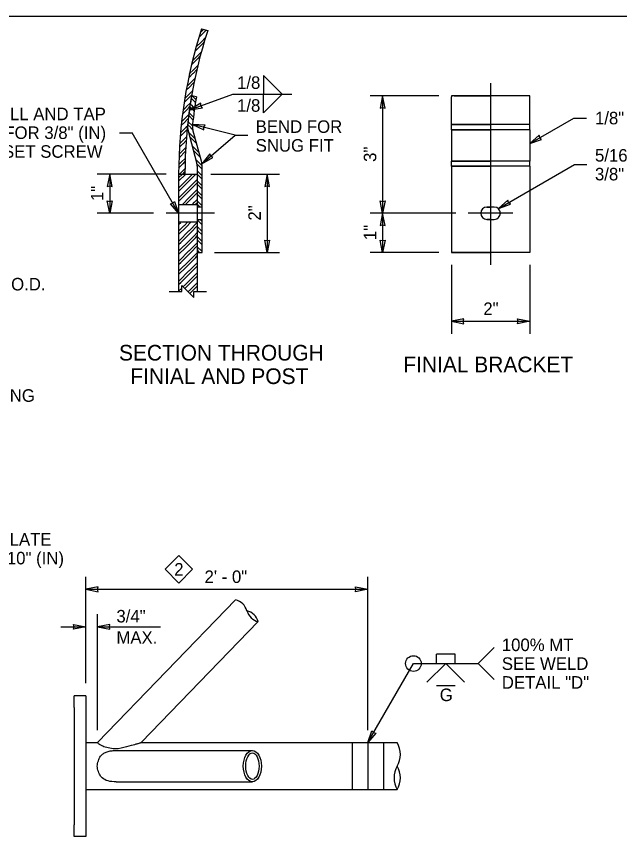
# Model space of a CAD drawing. Extents: x 99862 to 104211, y 98939 to 111076.
# Drawn here: x 101360 to 102130, y 107027 to 108075 of the extents above; entities that cross this region are included whole.
import ezdxf

# ---------------------------------------------------------------- set-up
doc = ezdxf.new("R2010")
doc.units = 0
for name, color, linetype in [('Level 10', 7, 'Continuous'), ('Level 15', 7, 'Continuous'), ('Level 2', 7, 'Continuous'), ('Level 20', 7, 'Continuous'), ('Level 3', 7, 'Continuous'), ('Level 5', 7, 'Continuous'), ('Level 6', 7, 'Continuous'), ('Level 60', 7, 'Continuous')]:
    doc.layers.add(name, color=color, linetype=linetype)

msp = doc.modelspace()

# ---------------------------------------------------------------- linework, layer by layer
at = {"layer": 'Level 10'}
for p, q in [((101675.6, 107999.7), (101699.5, 107975.8)), ((101675.6, 107999.7), (101675.6, 107975.7)), ((101581.5, 107955.7), (101636.4, 107975.8)), ((101636.4, 107975.8), (101711.5, 107975.8)), ((101675.6, 107951.9), (101675.6, 107975.9)), ((101675.6, 107951.9), (101699.5, 107975.8)), ((101920.3, 107260.2), (101896.3, 107260.2)), ((101896.3, 107248.2), (101896.3, 107260.2)), ((101920.3, 107248.2), (101920.3, 107260.2)), ((101896.3, 107220.2), (101920.3, 107220.2))]:
    msp.add_line(p, q, dxfattribs=at)
at = {"layer": 'Level 15'}
for p, q in [((101965.6, 107989.5), (101965.6, 107757.5)), ((101639.4, 107923.3), (101584.9, 107937.1)), ((102015.6, 107912.6), (102071.9, 107945.1)), ((102071.9, 107945.1), (102087.9, 107945.1)), ((101491.6, 107926.4), (101507.6, 107926.4)), ((101567.1, 107823.5), (101507.6, 107926.4)), ((101596.8, 107886.8), (101639.4, 107923.3)), ((101639.4, 107923.3), (101655.4, 107923.3)), ((101975.6, 107829.7), (102072.7, 107885.7)), ((102072.7, 107885.7), (102088.7, 107885.7)), ((101551.1, 107873.5), (101463.1, 107873.5)), ((101479.1, 107873.5), (101479.1, 107823.5)), ((101608.1, 107873.5), (101696.1, 107873.5)), ((101680.1, 107873.5), (101680.1, 107773.5)), ((101535.1, 107823.5), (101463.1, 107823.5)), ((101613, 107823.5), (101551.1, 107823.5)), ((101994.1, 107823.5), (101937.1, 107823.5)), ((101970.2, 107268.8), (101949.6, 107248.2)), ((101808.6, 107147.1), (101867, 107248.2)), ((101867, 107248.2), (101949.6, 107248.2)), ((101884.3, 107224.2), (101908.3, 107248.2)), ((101932.3, 107224.2), (101908.3, 107248.2)), ((101970.2, 107227.6), (101949.6, 107248.2))]:
    msp.add_line(p, q, dxfattribs=at)
for points in [[(101581.5, 107955.7), (101597.4, 107958.2), (101595.6, 107960.8), (101595.3, 107964)], [(101584.9, 107937.1), (101599.3, 107930.2), (101599.4, 107933.4), (101600.9, 107936.2)], [(102015.6, 107912.6), (102030.8, 107917.8), (102028.6, 107920.1), (102027.7, 107923.1)], [(101596.8, 107886.8), (101610.8, 107894.7), (101608.2, 107896.5), (101606.8, 107899.3)], [(101479.1, 107873.5), (101476, 107857.8), (101479.1, 107858.5), (101482.2, 107857.8)], [(101680.1, 107873.5), (101677, 107857.8), (101680.1, 107858.5), (101683.2, 107857.8)], [(101479.1, 107823.5), (101476, 107839.2), (101479.1, 107838.5), (101482.2, 107839.2)], [(101567.1, 107823.5), (101556.5, 107835.5), (101559.6, 107836.4), (101561.9, 107838.6)], [(101975.6, 107829.7), (101990.8, 107834.9), (101988.6, 107837.2), (101987.7, 107840.2)], [(101680.1, 107773.5), (101677, 107789.2), (101680.1, 107788.5), (101683.2, 107789.2)], [(101808.6, 107147.1), (101813.7, 107162.2), (101816.1, 107160.1), (101819.1, 107159.2)]]:
    msp.add_lwpolyline(points, close=True, dxfattribs=at)
msp.add_lwpolyline([(101555.2, 107723.5), (101571.2, 107723.5), (101571.2, 107731.2), (101586.7, 107715.7), (101586.7, 107723.5), (101602.7, 107723.5)], dxfattribs=at)
msp.add_circle((101867, 107248.2), 10, dxfattribs=at)
at = {"layer": 'Level 2'}
for p, q in [((101899.6, 107973.4), (101811.6, 107973.4)), ((101827.6, 107973.4), (101827.6, 107823.5)), ((101921.1, 107823.5), (101811.6, 107823.5)), ((101827.6, 107823.5), (101827.6, 107773.5)), ((101613, 107773.5), (101696.1, 107773.5)), ((101899.6, 107773.5), (101811.6, 107773.5)), ((101915.6, 107757.5), (101915.6, 107669.5)), ((102015.6, 107757.5), (102015.6, 107669.5)), ((101915.6, 107685.5), (102015.6, 107685.5))]:
    msp.add_line(p, q, dxfattribs=at)
for points in [[(101827.6, 107973.4), (101824.5, 107957.7), (101827.6, 107958.4), (101830.7, 107957.7)], [(101827.6, 107823.5), (101824.5, 107839.2), (101827.6, 107838.5), (101830.7, 107839.2)], [(101827.6, 107823.5), (101824.5, 107807.8), (101827.6, 107808.5), (101830.7, 107807.8)], [(101827.6, 107773.5), (101824.5, 107789.2), (101827.6, 107788.5), (101830.7, 107789.2)], [(101915.6, 107685.5), (101931.4, 107682.4), (101930.6, 107685.5), (101931.4, 107688.6)], [(102015.6, 107685.5), (101999.9, 107682.4), (102000.6, 107685.5), (101999.9, 107688.6)]]:
    msp.add_lwpolyline(points, close=True, dxfattribs=at)
at = {"layer": 'Level 20'}
msp.add_lwpolyline([(101567.5, 107386.1), (101585, 107368.6), (101567.5, 107351), (101549.9, 107368.6)], close=True, dxfattribs=at)
at = {"layer": 'Level 3'}
for p, q in [((101596.5, 108059), (101604.2, 108056.8)), ((101567.1, 107873.5), (101567.1, 107873.5)), ((101567.1, 107873.5), (101567.1, 107723.5)), ((101567.1, 107873.5), (101579.6, 107873.5)), ((101567.1, 107864.3), (101576.2, 107873.5)), ((101567.1, 107868.6), (101572, 107873.5)), ((101579.6, 107873.5), (101590.8, 107873.5)), ((101579.6, 107873.5), (101579.6, 107873.5)), ((101581, 107869.6), (101584.8, 107873.5)), ((101583.1, 107867.5), (101589.1, 107873.5)), ((101590.8, 107873.5), (101590.8, 107723.5)), ((101568.1, 107856.8), (101580.9, 107869.5)), ((101570.3, 107854.7), (101583, 107867.4)), ((101574.5, 107850.4), (101587.3, 107863.1)), ((101587.4, 107863.2), (101590.8, 107866.6)), ((101589.5, 107861.1), (101590.8, 107862.4)), ((101567.1, 107855.7), (101568.1, 107856.7)), ((101567.1, 107851.5), (101570.2, 107854.6)), ((101576.7, 107848.3), (101589.4, 107861)), ((101581, 107844), (101590.8, 107853.8)), ((101567.1, 107842.9), (101574.5, 107850.3)), ((101567.1, 107838.7), (101576.6, 107848.2)), ((101571.4, 107834.4), (101580.9, 107843.9)), ((101575.6, 107834.4), (101583, 107841.8)), ((101583.1, 107841.9), (101590.8, 107849.6)), ((101587.4, 107837.6), (101590.8, 107841)), ((101590.8, 107834.4), (101567.1, 107834.4)), ((101584.2, 107834.4), (101587.3, 107837.5)), ((101588.5, 107834.4), (101589.4, 107835.4)), ((101589.5, 107835.5), (101590.8, 107836.7)), ((101567.1, 107812.6), (101590.8, 107812.6)), ((101567.1, 107809.3), (101569.7, 107811.8)), ((101569.7, 107811.9), (101570.4, 107812.6)), ((101574, 107807.6), (101578.9, 107812.6)), ((101576.2, 107805.5), (101583.2, 107812.6)), ((101580.4, 107801.2), (101590.8, 107811.6)), ((101567.1, 107800.7), (101573.9, 107807.6)), ((101567.1, 107796.4), (101576.1, 107805.4)), ((101567.6, 107788.4), (101580.3, 107801.2)), ((101569.7, 107786.3), (101582.5, 107799)), ((101582.6, 107799.1), (101590.8, 107807.3)), ((101574, 107782), (101586.8, 107794.7)), ((101576.2, 107779.9), (101588.9, 107792.6)), ((101586.8, 107794.8), (101590.8, 107798.8)), ((101589, 107792.7), (101590.8, 107794.5)), ((101567.1, 107787.9), (101567.5, 107788.3)), ((101567.1, 107783.6), (101569.7, 107786.2)), ((101567.1, 107775.1), (101573.9, 107781.9)), ((101567.1, 107770.8), (101576.1, 107779.8)), ((101580.4, 107775.6), (101590.8, 107785.9)), ((101582.6, 107773.5), (101590.8, 107781.7)), ((101567.6, 107762.8), (101580.3, 107775.5)), ((101569.7, 107760.7), (101582.5, 107773.4)), ((101574, 107756.4), (101586.8, 107769.1)), ((101586.8, 107769.2), (101590.8, 107773.1)), ((101589, 107767.1), (101590.8, 107768.9)), ((101567.1, 107762.2), (101567.5, 107762.7)), ((101567.1, 107758), (101569.7, 107760.6)), ((101576.2, 107754.3), (101588.9, 107767)), ((101580.4, 107750), (101590.8, 107760.3)), ((101567.1, 107749.4), (101573.9, 107756.3)), ((101567.1, 107745.2), (101576.1, 107754.2)), ((101567.6, 107737.2), (101580.3, 107749.9)), ((101569.7, 107735), (101582.5, 107747.8)), ((101582.6, 107747.9), (101590.8, 107756.1)), ((101586.8, 107743.6), (101590.8, 107747.5)), ((101567.1, 107736.6), (101567.5, 107737.1)), ((101574, 107730.8), (101586.8, 107743.5)), ((101576.2, 107728.6), (101588.9, 107741.4)), ((101589, 107741.4), (101590.8, 107743.2)), ((101567.1, 107732.4), (101569.7, 107735)), ((101567.1, 107723.8), (101571.2, 107727.9)), ((101572.8, 107729.6), (101573.9, 107730.7)), ((101575, 107727.4), (101576.1, 107728.5)), ((101580.4, 107724.3), (101590.8, 107734.7)), ((101582.6, 107722.2), (101590.8, 107730.4)), ((101571, 107723.5), (101571.2, 107723.7)), ((101579.3, 107723.2), (101580.3, 107724.3)), ((101581.4, 107721), (101582.5, 107722.1)), ((101585.7, 107716.7), (101586.7, 107717.8))]:
    msp.add_line(p, q, dxfattribs=at)
at = {"layer": 'Level 5'}
for p, q in [((101593.3, 108048.3), (101602.3, 108057.3)), ((101595.1, 108054.3), (101599, 108058.3)), ((101587.9, 108030), (101598.2, 108040.4)), ((101589.6, 108036.1), (101596.1, 108042.5)), ((101596.2, 108042.6), (101601.6, 108048)), ((101598.3, 108040.5), (101599.8, 108041.9)), ((101589.8, 108023.4), (101596.2, 108029.8)), ((101583.7, 108013.1), (101591.8, 108021.2)), ((101585.1, 108018.7), (101589.7, 108023.3)), ((101591.9, 108021.2), (101594.8, 108024.2)), ((101583.4, 108004.1), (101591.9, 108012.7)), ((101579.9, 107996.4), (101585.4, 108001.9)), ((101581, 108001.8), (101583.3, 108004.1)), ((101585.5, 108002), (101590.5, 108007.1)), ((101577.9, 107985.9), (101588.1, 107996.1)), ((101579.1, 107982.8), (101587.1, 107990.8)), ((101574.9, 107970.1), (101583.3, 107978.4)), ((101576.9, 107980.6), (101579, 107982.7)), ((101583.4, 107978.5), (101585, 107980.1)), ((101574.2, 107965.2), (101583.9, 107974.9)), ((101583.2, 107970.7), (101588.7, 107965.2)), ((101589.8, 107972.4), (101583.7, 107973.5)), ((101584.8, 107973.3), (101589.2, 107968.9)), ((101915.6, 107973.4), (101915.6, 107972.4)), ((101915.6, 107937.1), (101915.6, 107972.4)), ((102015.6, 107973.5), (101918.9, 107973.5)), ((101918.9, 107973.5), (101965.6, 107973.5)), ((102015.6, 107937.1), (102015.6, 107973.5)), ((101572.2, 107950.3), (101579, 107957.1)), ((101572.8, 107955.2), (101576.9, 107959.2)), ((101576.9, 107959.3), (101582.3, 107964.6)), ((101579.1, 107957.2), (101581.6, 107959.7)), ((101581.5, 107959.6), (101582.6, 107958.5)), ((101582, 107963.3), (101584.7, 107960.6)), ((101582.7, 107958.4), (101587.1, 107953.9)), ((101584.8, 107960.5), (101587.6, 107957.7)), ((101570.8, 107940.4), (101580.3, 107949.8)), ((101580, 107948.2), (101585.6, 107942.6)), ((101580.5, 107952), (101586.1, 107946.4)), ((101570.4, 107935.7), (101572.6, 107937.9)), ((101572.7, 107937.9), (101579.6, 107944.9)), ((101578.6, 107936.8), (101582.6, 107932.9)), ((101579, 107940.6), (101584.7, 107935)), ((101915.6, 107930.2), (101915.6, 107937.1)), ((102015.6, 107937.1), (101915.6, 107937.1)), ((101915.6, 107937.1), (101965.6, 107937.1)), ((102015.6, 107930.2), (102015.6, 107937.1)), ((101569.2, 107921.6), (101578, 107930.4)), ((101569.6, 107926.3), (101576.9, 107933.6)), ((101576.9, 107933.7), (101578.4, 107935.1)), ((101579.4, 107928.6), (101590.1, 107888.4)), ((101579.8, 107927.1), (101588.6, 107918.3)), ((101582.7, 107932.8), (101585.5, 107930)), ((101584.8, 107934.9), (101584.8, 107934.8)), ((101596.2, 107890), (101585.4, 107930.2)), ((102015.6, 107930.2), (101915.6, 107930.2)), ((101915.6, 107930.2), (101965.6, 107930.2)), ((101915.6, 107930.2), (101915.6, 107890)), ((102015.6, 107930.2), (102015.6, 107890)), ((101568.3, 107912.2), (101570.4, 107914.3)), ((101570.5, 107914.4), (101577.3, 107921.2)), ((101572.7, 107912.3), (101576.9, 107916.6)), ((101581.3, 107921.3), (101589, 107913.6)), ((101567.8, 107898.9), (101576.2, 107907.3)), ((101568.1, 107907.8), (101572.6, 107912.2)), ((101584.4, 107909.6), (101584.7, 107909.3)), ((101584.8, 107909.3), (101593.3, 107900.8)), ((101586, 107903.8), (101594.8, 107895)), ((101589.1, 107913.5), (101590.1, 107912.5)), ((101567.6, 107894.5), (101575.9, 107902.7)), ((101570.5, 107888.8), (101575.7, 107893.9)), ((101567.1, 107881.1), (101572.6, 107886.6)), ((101567.3, 107885.6), (101570.4, 107888.7)), ((101572.7, 107886.7), (101575.6, 107889.6)), ((101589.1, 107892.1), (101591.1, 107890.1)), ((101590.4, 107886.6), (101597, 107880)), ((101590.8, 107883.5), (101590.8, 107773.5)), ((101591.2, 107890), (101596.9, 107884.3)), ((101597, 107773.5), (101597, 107883.5)), ((102015.6, 107890), (101915.6, 107890)), ((101915.6, 107890), (101965.6, 107890)), ((101915.6, 107883.5), (101915.6, 107890)), ((102015.6, 107883.5), (101915.6, 107883.5)), ((101915.6, 107883.5), (101965.6, 107883.5)), ((101915.6, 107883.5), (101915.6, 107773.5)), ((102015.6, 107883.5), (102015.6, 107890)), ((102015.6, 107883.5), (102015.6, 107773.5)), ((101567.1, 107873.5), (101575.1, 107873.5)), ((101568, 107873.5), (101575.3, 107880.8)), ((101572.3, 107873.5), (101575.2, 107876.4)), ((101590.8, 107877.6), (101597, 107871.4)), ((101590.8, 107873.4), (101595.4, 107868.8)), ((101590.8, 107864.8), (101591.1, 107864.5)), ((101591.2, 107864.4), (101597, 107858.6)), ((101595.5, 107868.7), (101597, 107867.1)), ((101590.8, 107860.6), (101597, 107854.3)), ((101590.8, 107852), (101597, 107845.8)), ((101590.8, 107847.8), (101595.4, 107843.1)), ((101595.5, 107843.1), (101597, 107841.5)), ((101590.8, 107839.2), (101591.1, 107838.9)), ((101590.8, 107834.9), (101594.4, 107831.3)), ((101597, 107831.3), (101590.8, 107831.3)), ((101591.2, 107838.8), (101597, 107832.9)), ((101597, 107831), (101597, 107831.3)), ((101970.3, 107831.3), (101960.9, 107831.3)), ((101960.9, 107831.3), (101965.6, 107831.3)), ((101590.8, 107815.7), (101597, 107815.7)), ((101590.8, 107815), (101597, 107808.8)), ((101590.8, 107812.6), (101590.8, 107773.5)), ((101594.4, 107815.7), (101597, 107813)), ((101597, 107815.7), (101597, 107815.9)), ((101965.6, 107815.7), (101960.9, 107815.7)), ((101960.9, 107815.7), (101970.3, 107815.7)), ((101590.8, 107806.5), (101593.9, 107803.4)), ((101590.8, 107802.2), (101591.7, 107801.2)), ((101591.8, 107801.2), (101597, 107796)), ((101594, 107803.3), (101597, 107800.2)), ((101590.8, 107793.6), (101597, 107787.4)), ((101590.8, 107789.4), (101597, 107783.2)), ((101590.8, 107780.8), (101593.9, 107777.7)), ((101590.8, 107776.6), (101591.7, 107775.6)), ((101590.8, 107773.5), (101597, 107773.5)), ((101591.8, 107775.5), (101593.9, 107773.5)), ((101594, 107777.6), (101597, 107774.6)), ((101915.6, 107773.5), (101965.6, 107773.5)), ((102015.6, 107773.5), (101915.6, 107773.5))]:
    msp.add_line(p, q, dxfattribs=at)
for centre, radius, start, end in [((102167.1, 107873.5), 600, 161.9884, 180), ((102168.9, 107873.2), 593.8, 161.9884, 179.9699), ((102165.8, 107873.5), 590.6, 170.2522, 173.7514), ((102165.8, 107873.5), 584.4, 170.2522, 173.7514), ((101603.5, 107935.1), 25, 173.7514, 195), ((101603.5, 107935.1), 18.8, 173.7514, 195), ((101572, 107883.5), 18.8, 0, 15), ((101572, 107883.5), 25, 0, 15), ((101960.9, 107823.5), 7.81, 90, 270), ((101970.3, 107823.5), 7.81, 270, 90)]:
    msp.add_arc(centre, radius, start, end, dxfattribs=at)
msp.add_ellipse((101965.6, 107873.3), major_axis=(-593.7, 0), ratio=0.169312, start_param=4.791199, end_param=4.796699, dxfattribs=at)
at = {"layer": 'Level 6'}
for p, q in [((101448.6, 107223.1), (101448.6, 107359.1)), ((101808.6, 107163.1), (101808.6, 107359.1)), ((101448.6, 107343.1), (101808.6, 107343.1)), ((101463.6, 107147.1), (101639.9, 107329.5)), ((101463.6, 107163.1), (101463.6, 107311.1)), ((101519.2, 107147.1), (101668.7, 107301.7)), ((101416.6, 107295.1), (101448.6, 107295.1)), ((101463.6, 107295.1), (101544, 107295.1)), ((101448.6, 107207.1), (101433.6, 107207.1)), ((101433.6, 107192.1), (101433.6, 107207.1)), ((101448.6, 107207.1), (101448.6, 107027.1)), ((101433.6, 107192.1), (101433.6, 107042.1)), ((101448.6, 107147.1), (101463.6, 107147.1)), ((101519.2, 107147.1), (101846.3, 107147.1)), ((101788.6, 107147.1), (101788.6, 107087.1)), ((101808.6, 107147.1), (101808.6, 107087.1)), ((101828.6, 107147.1), (101828.6, 107087.1)), ((101487.3, 107137.1), (101661.3, 107137.1)), ((101487.3, 107097.1), (101661.3, 107097.1)), ((101448.6, 107087.1), (101846.3, 107087.1)), ((101433.6, 107027.1), (101433.6, 107042.1)), ((101448.6, 107027.1), (101433.6, 107027.1))]:
    msp.add_line(p, q, dxfattribs=at)
for points in [[(101448.6, 107343.1), (101464.3, 107340), (101463.6, 107343.1), (101464.3, 107346.2)], [(101808.6, 107343.1), (101792.8, 107340), (101793.6, 107343.1), (101792.8, 107346.2)], [(101448.6, 107295.1), (101432.8, 107292), (101433.6, 107295.1), (101432.8, 107298.2)], [(101463.6, 107295.1), (101479.3, 107292), (101478.6, 107295.1), (101479.3, 107298.2)]]:
    msp.add_lwpolyline(points, close=True, dxfattribs=at)
for centre, radius, start, end in [((101635.1, 107310.1), 20, 15.9593, 75.9593), ((101649.5, 107296.2), 20, 15.9593, 75.9593), ((101673.6, 107321.1), 20, 195.9593, 255.9593), ((101820.3, 107132.1), 30, 330, 30), ((101872.2, 107102.1), 30, 150, 210), ((101820.3, 107102.1), 30, 330, 30)]:
    msp.add_arc(centre, radius, start, end, dxfattribs=at)
for major_axis, ratio in [((0, 20), 0.579418), ((0, 16.9), 0.501532)]:
    msp.add_ellipse((101661.3, 107117.1), major_axis=major_axis, ratio=ratio, dxfattribs=at)
for points, degree in [([(101463.6, 107147.1), (101463.5, 107147.1), (101463.5, 107147.1), (101463.5, 107147.1)], 2), ([(101519.2, 107147.1), (101519.2, 107147.1), (101519.2, 107147.1), (101519.1, 107147.1), (101518.6, 107146.9), (101517.2, 107146.4), (101515.1, 107145.8), (101512.3, 107144.9), (101501, 107141.8), (101486.4, 107137.7), (101467.6, 107142.5), (101463.6, 107147.4), (101463.6, 107147), (101463.6, 107147.1)], 3), ([(101487.3, 107097.1), (101483.8, 107097.1), (101476.2, 107097.6), (101468.8, 107101.9), (101465.9, 107106.7), (101463.1, 107113.4), (101463.1, 107120.8), (101465.9, 107127.4), (101467.2, 107129.7), (101469, 107131.6), (101470.6, 107133), (101472.4, 107134.1), (101474.5, 107135.1), (101476.9, 107135.9), (101479.5, 107136.5), (101482.5, 107136.9), (101484.8, 107137), (101486.5, 107137.1), (101487, 107137.1), (101487.3, 107137.1)], 3)]:
    msp.add_open_spline(points, degree=degree, dxfattribs=at)
at = {"layer": 'Level 60'}
msp.add_line((103150, 108075), (100000, 108075), dxfattribs=at)

# ---------------------------------------------------------------- texts
at = {"layer": 'Level 10'}
msp.add_text('1/8', height=16, rotation=360, dxfattribs=at).set_placement((101641.7, 107982.4))
for s, p in [('1/8', (101641.7, 107953.2)), ('100% MT', (101979.9, 107264.1)), ('SEE WELD ', (101979.9, 107240.1)), ('DETAIL "D"', (101979.9, 107216.1)), ('G', (101900.6, 107200.2))]:
    msp.add_text(s, height=16, dxfattribs=at).set_placement(p)
at = {"layer": 'Level 2'}
msp.add_text('3"', height=16, rotation=90, dxfattribs=at).set_placement((101819.6, 107889.1))
at = {"layer": 'Level 20'}
for s, height, p in [('DRILL AND TAP', 16, (101314.8, 107942.4)), ('1/8" (IN) PLATE MIN.', 16, (102098.9, 107937.1)), ('WALL FOR 3/8" (IN)', 16, (101280.2, 107918.4)), ('BEND FOR', 16, (101665.5, 107926.2)), ('SNUG FIT', 16, (101665.5, 107902.2)), (' S.S. ALLEN SET SCREW', 16, (101216.7, 107894.4)), ('5/16" (IN) x 1/2" (IN) SLOT FOR', 16, (102098.9, 107889.5)), ('3/8" (IN) S.S. ALLEN SET SCREW', 16, (102098.9, 107865.5)), ('PIPE O.D.', 16, (101298.4, 107724.9)), ('2"', 16, (101956.3, 107693.5)), ('SECTION THROUGH', 20, (101490.9, 107635.3)), ('FINIAL BRACKET', 20, (101854.1, 107620.3)), ('FINIAL AND POST', 20, (101505.4, 107605.3)), ('BACK-UP RING', 16, (101228.9, 107582.6)), ('1/4" (IN) PLATE', 16, (101252.1, 107398.9)), ('10" (IN) x 10" (IN)', 16, (101252.1, 107374.9)), ('2', 16, (101561.5, 107360.6)), ('2\' - 0"', 16, (101600.2, 107351.1)), ('3/4" ', 16, (101487.6, 107300.7)), ('MAX.', 16, (101487.6, 107273.5))]:
    msp.add_text(s, height=height, dxfattribs=at).set_placement(p)
for s, p in [('1"', (101471.1, 107839.1)), ('2"', (101672.1, 107814.1)), ('1"', (101819.6, 107789.1))]:
    msp.add_text(s, height=16, rotation=90, dxfattribs=at).set_placement(p)

doc.saveas('drawing.dxf')
